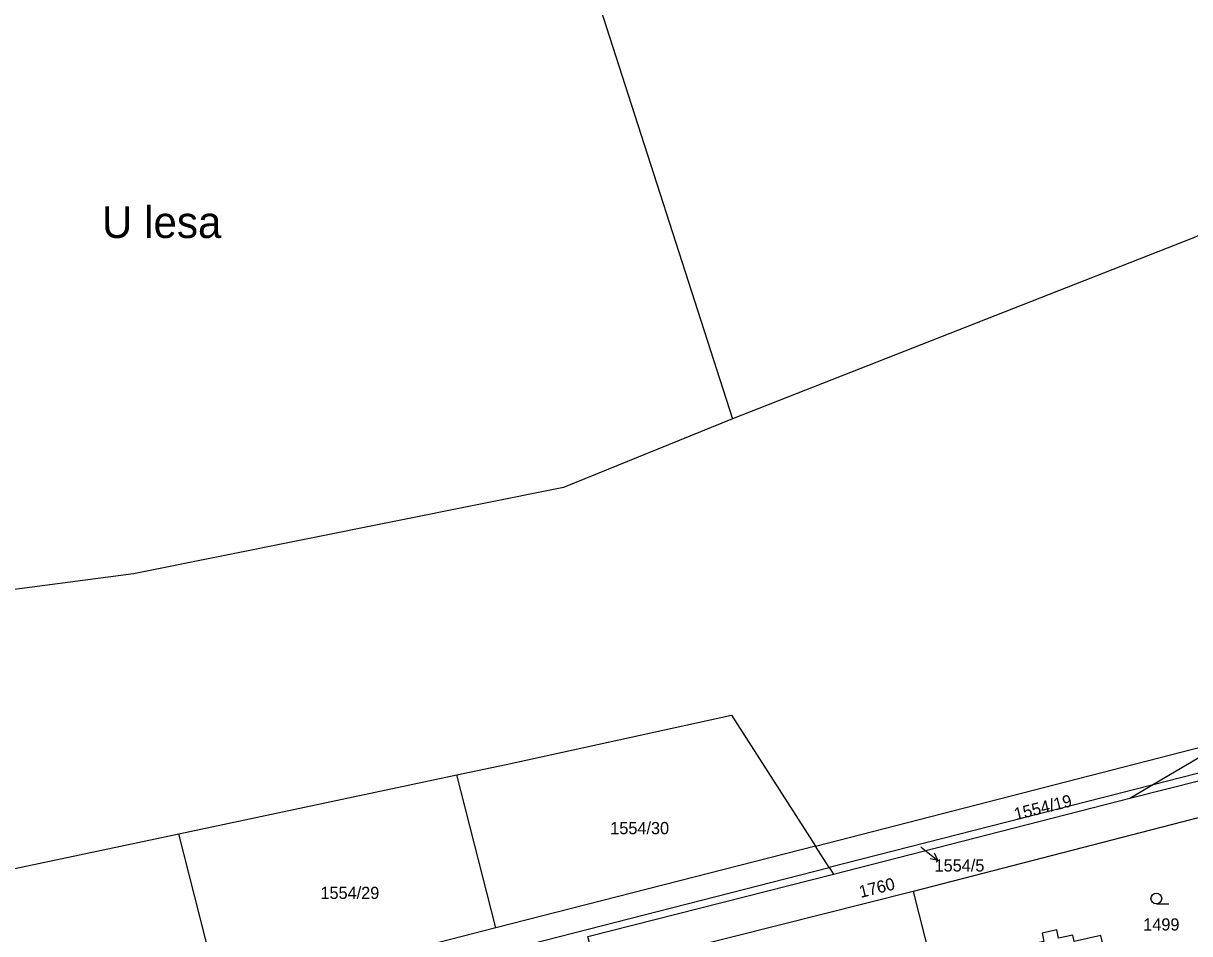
# Model space of a CAD drawing. Extents: x -724107 to -720612, y -1045267 to -1038441.
# Drawn here: x -722795.4 to -722632.6, y -1044034.9 to -1043907.9 of the extents above; entities that cross this region are included whole.
import ezdxf

# ---------------------------------------------------------------- set-up
doc = ezdxf.new("R2010")
doc.units = 0
for name, color, linetype in [('Hranice parcel', 7, 'Continuous'), ('Parcelní čísla', 7, 'Continuous'), ('Pop  PČ popisy', 7, 'Continuous'), ('Značky kultur', 7, 'Continuous')]:
    doc.layers.add(name, color=color, linetype=linetype)

msp = doc.modelspace()

# ---------------------------------------------------------------- linework, layer by layer
at = {"layer": 'Hranice parcel'}
for p, q in [((-722717.28, -1043898.15), (-722696.39, -1043963.11)), ((-722684.79, -1044022.74), (-722627.13, -1044007.89)), ((-722637.84, -1044014.22), (-722627.13, -1044007.89)), ((-722773.7, -1044021.01), (-722734.87, -1044012.8)), ((-722729.42, -1044034.14), (-722734.87, -1044012.8)), ((-722637.84, -1044014.22), (-722682.88, -1044025.72)), ((-722640.93, -1044016.05), (-722637.84, -1044014.22)), ((-722682.3, -1044026.63), (-722640.93, -1044016.05)), ((-722629.57, -1044018.3), (-722671.18, -1044029.05)), ((-722812.22, -1044029.16), (-722773.7, -1044021.01)), ((-722767.85, -1044043.95), (-722773.7, -1044021.01)), ((-722684.79, -1044022.74), (-722729.42, -1044034.14)), ((-722682.88, -1044025.72), (-722684.79, -1044022.74)), ((-722682.88, -1044025.72), (-722682.3, -1044026.63)), ((-722671.18, -1044029.05), (-722715.32, -1044040.15)), ((-722671.18, -1044029.05), (-722665.46, -1044051.37)), ((-722729.42, -1044034.14), (-722767.85, -1044043.95))]:
    msp.add_line(p, q, dxfattribs=at)
for points in [[(-722560.5, -1043904.93), (-722632.01, -1043937.87), (-722696.39, -1043963.11)], [(-722696.39, -1043963.11), (-722719.96, -1043972.68), (-722780, -1043984.73), (-722828.87, -1043991.13)], [(-722502.67, -1043979.69), (-722543.27, -1043990.07), (-722567.77, -1043996.33), (-722637.84, -1044014.22)], [(-722734.87, -1044012.8), (-722727.96, -1044011.34), (-722696.54, -1044004.44), (-722684.79, -1044022.74)], [(-722640.93, -1044016.05), (-722630.77, -1044013.48), (-722629.57, -1044018.3)], [(-722800.37, -1044055.72), (-722744.36, -1044041.42), (-722682.88, -1044025.72)], [(-722715.32, -1044040.15), (-722716.6, -1044035.35), (-722682.3, -1044026.63)], [(-722641.65, -1044043.39), (-722643.22, -1044037.13), (-722644.47, -1044037.4), (-722644.95, -1044035.2), (-722648.7, -1044036.02), (-722648.89, -1044035.16), (-722650.86, -1044035.59), (-722651.12, -1044034.42), (-722653.16, -1044034.87), (-722652.91, -1044036.04), (-722653.58, -1044036.19), (-722651.97, -1044043.47), (-722645.16, -1044041.97), (-722644.69, -1044044.06), (-722641.65, -1044043.39)]]:
    msp.add_lwpolyline(points, dxfattribs=at)
at = {"layer": 'Pop  PČ popisy'}
for p, q in [((-722670.04, -1044022.85), (-722670.09, -1044022.85)), ((-722670.04, -1044022.85), (-722667.71, -1044024.74)), ((-722667.71, -1044024.74), (-722668.8, -1044024.5)), ((-722667.71, -1044024.74), (-722668.17, -1044023.72))]:
    msp.add_line(p, q, dxfattribs=at)
at = {"layer": 'Značky kultur'}
msp.add_line((-722637.21, -1044030.79), (-722635.46, -1044030.79), dxfattribs=at)
msp.add_circle((-722637.21, -1044030.04), 0.75, dxfattribs=at)

# ---------------------------------------------------------------- texts
at = {"layer": 'Parcelní čísla'}
for s, p in [('1554/19', (-722656.84, -1044019.13)), ('1760', (-722678.48, -1044029.96))]:
    msp.add_text(s, height=1.7, rotation=14, dxfattribs=at).set_placement(p)
for s, p in [('1554/30', (-722713.45, -1044021.06)), ('1554/5', (-722668.17, -1044026.27)), ('1554/29', (-722753.91, -1044030.1)), ('1499', (-722639.04, -1044034.51))]:
    msp.add_text(s, height=1.7, dxfattribs=at).set_placement(p)
at = {"layer": 'Pop  PČ popisy'}
msp.add_text('U lesa', height=4.4, dxfattribs=at).set_placement((-722784.41, -1043937.87))

doc.saveas('drawing.dxf')
